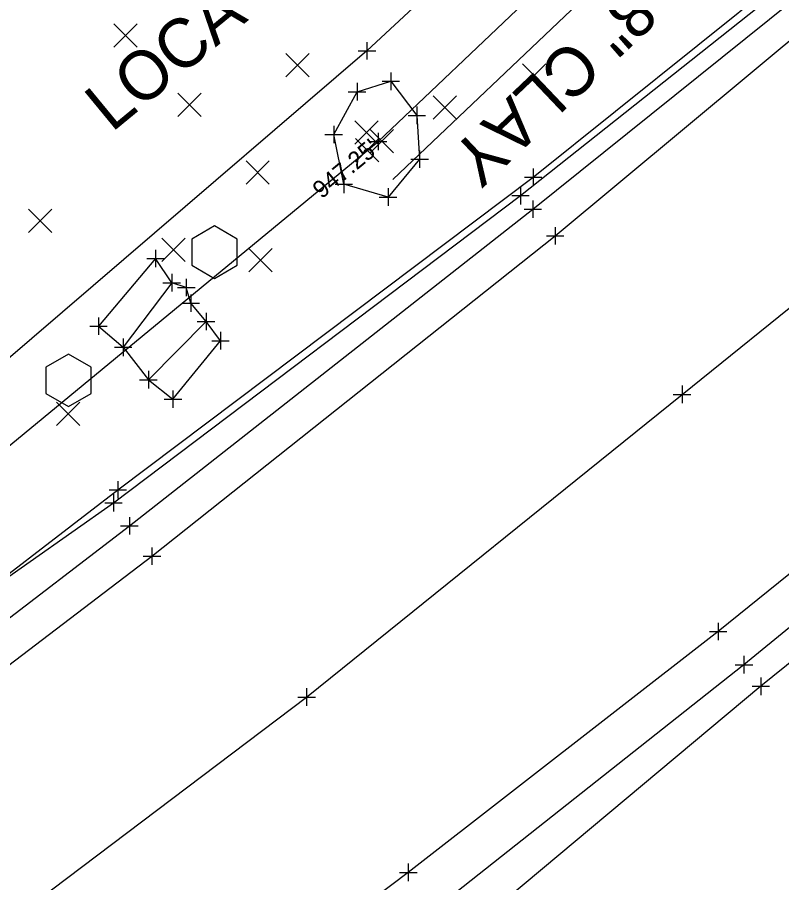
# Model space of a CAD drawing. Extents: x -4 to 139204, y -4 to 477121.
# Drawn here: x 139035.52 to 139079.26, y 476967.42 to 477016.92 of the extents above; entities that cross this region are included whole.
import ezdxf

# ---------------------------------------------------------------- set-up
doc = ezdxf.new("R2010")
doc.units = 0
for name, color, linetype in [('DR_X_Storm_Sewer', 7, 'Continuous'), ('DR_X_Text', 7, 'Continuous'), ('GE_X_Alignment', 7, 'Continuous'), ('GE_X_Alignment_100_Bearings', 7, 'Continuous'), ('GE_X_Alignment_100_Distances', 7, 'Continuous'), ('PM_X_Edge_Line', 7, 'Continuous'), ('PM_X_Surveyed_Line', 7, 'Continuous'), ('PV_X_COP', 7, 'Continuous'), ('PV_X_EOP', 7, 'Continuous'), ('PV_X_Shoulder', 7, 'Continuous'), ('PV_X_Shoulder_Aggregate', 7, 'Continuous'), ('RD_X_Concrete_Pad', 7, 'Continuous'), ('RD_X_Fence', 7, 'Continuous'), ('RD_X_GR_Lt', 7, 'Continuous'), ('RW_X_Esmt_SH', 7, 'Continuous'), ('SC_Scratch1', 7, 'Continuous'), ('SV_X_Text', 7, 'Continuous')]:
    doc.layers.add(name, color=color, linetype=linetype)

msp = doc.modelspace()

# ---------------------------------------------------------------- linework, layer by layer
at = {"layer": 'DR_X_Storm_Sewer'}
for p in [(139072.001, 477024.857), (138978.284, 476945.603)]:
    msp.add_line(p, (139056.168, 477009.808), dxfattribs=at)
at = {"layer": 'DR_X_Text'}
msp.add_line((139057.01, 477007.643), (139071.222, 477021.15), dxfattribs=at)
at = {"layer": 'GE_X_Alignment'}
for p, q in [((139041.05, 477015.206), (139042.384, 477016.541)), ((139041.05, 477016.541), (139042.384, 477015.206)), ((139050.88, 477013.504), (139052.214, 477014.84)), ((139050.88, 477014.84), (139052.214, 477013.504)), ((139064.431, 477012.923), (139065.765, 477014.258)), ((139064.431, 477014.258), (139065.765, 477012.923)), ((139044.7, 477011.238), (139046.034, 477012.573)), ((139044.7, 477012.573), (139046.034, 477011.238)), ((139059.326, 477011.084), (139060.66, 477012.418)), ((139059.326, 477012.418), (139060.66, 477011.084)), ((139054.839, 477009.653), (139056.173, 477010.988)), ((139054.839, 477010.988), (139056.173, 477009.653)), ((139055.708, 477009.166), (139057.042, 477010.502)), ((139055.708, 477010.502), (139057.042, 477009.166)), ((139054.876, 477008.658), (139056.21, 477009.993)), ((139054.876, 477009.993), (139056.21, 477008.658)), ((139048.608, 477007.38), (139049.942, 477008.715)), ((139048.608, 477008.715), (139049.942, 477007.38)), ((139036.17, 477004.601), (139037.504, 477005.935)), ((139036.17, 477005.935), (139037.504, 477004.601)), ((139043.783, 477002.952), (139045.117, 477004.287)), ((139043.783, 477004.287), (139045.117, 477002.952)), ((139048.767, 477002.362), (139050.101, 477003.698)), ((139048.767, 477003.698), (139050.101, 477002.362)), ((139037.762, 476993.565), (139039.096, 476994.9)), ((139037.762, 476994.9), (139039.096, 476993.565))]:
    msp.add_line(p, q, dxfattribs=at)
at = {"layer": 'GE_X_Alignment_100_Bearings'}
for p, q in [((139055.528, 477015.497), (139055.528, 477014.497)), ((139055.028, 477014.997), (139056.028, 477014.997)), ((139055.528, 477014.997), (139055.528, 477014.997)), ((139056.894, 477013.757), (139056.894, 477012.757)), ((139054.959, 477013.161), (139054.959, 477012.161)), ((139056.394, 477013.257), (139057.394, 477013.257)), ((139056.894, 477013.257), (139056.894, 477013.257)), ((139054.459, 477012.661), (139055.459, 477012.661)), ((139054.959, 477012.661), (139054.959, 477012.661)), ((139058.383, 477011.807), (139058.383, 477010.807)), ((139057.883, 477011.307), (139058.883, 477011.307)), ((139058.383, 477011.307), (139058.383, 477011.307)), ((139053.626, 477010.708), (139053.626, 477009.708)), ((139053.126, 477010.208), (139054.126, 477010.208)), ((139053.626, 477010.208), (139053.626, 477010.208)), ((139058.543, 477009.298), (139058.543, 477008.298)), ((139058.043, 477008.798), (139059.043, 477008.798)), ((139058.543, 477008.798), (139058.543, 477008.798)), ((139065.043, 477008.277), (139065.043, 477007.277)), ((139054.202, 477007.867), (139054.202, 477006.867)), ((139064.543, 477007.777), (139065.543, 477007.777)), ((139065.043, 477007.777), (139065.043, 477007.777)), ((139053.702, 477007.367), (139054.702, 477007.367)), ((139054.202, 477007.367), (139054.202, 477007.367)), ((139056.734, 477007.135), (139056.734, 477006.135)), ((139064.316, 477007.215), (139064.316, 477006.215)), ((139056.234, 477006.635), (139057.234, 477006.635)), ((139056.734, 477006.635), (139056.734, 477006.635)), ((139063.816, 477006.715), (139064.816, 477006.715)), ((139064.316, 477006.715), (139064.316, 477006.715)), ((139065.015, 477006.445), (139065.015, 477005.445)), ((139064.515, 477005.945), (139065.515, 477005.945)), ((139065.015, 477005.945), (139065.015, 477005.945)), ((139066.294, 477004.913), (139066.294, 477003.913)), ((139066.294, 477004.913), (139066.294, 477003.913)), ((139065.794, 477004.413), (139066.794, 477004.413)), ((139065.794, 477004.413), (139066.794, 477004.413)), ((139066.294, 477004.413), (139066.294, 477004.413)), ((139066.294, 477004.413), (139066.294, 477004.413)), ((139043.433, 477003.617), (139043.433, 477002.617)), ((139042.933, 477003.117), (139043.933, 477003.117)), ((139043.433, 477003.117), (139043.433, 477003.117)), ((139044.354, 477002.237), (139044.354, 477001.237)), ((139043.854, 477001.737), (139044.854, 477001.737)), ((139044.354, 477001.737), (139044.354, 477001.737)), ((139045.19, 477001.96), (139045.19, 477000.96)), ((139044.69, 477001.46), (139045.69, 477001.46)), ((139045.19, 477001.46), (139045.19, 477001.46)), ((139045.455, 477001.071), (139045.455, 477000.071)), ((139044.955, 477000.571), (139045.955, 477000.571)), ((139045.455, 477000.571), (139045.455, 477000.571)), ((139040.166, 476999.754), (139040.166, 476998.754)), ((139046.32, 477000.018), (139046.32, 476999.018)), ((139039.666, 476999.254), (139040.666, 476999.254)), ((139040.166, 476999.254), (139040.166, 476999.254)), ((139045.82, 476999.518), (139046.82, 476999.518)), ((139046.32, 476999.518), (139046.32, 476999.518)), ((139047.149, 476998.921), (139047.149, 476997.921)), ((139041.578, 476998.542), (139041.578, 476997.542)), ((139046.649, 476998.421), (139047.649, 476998.421)), ((139047.149, 476998.421), (139047.149, 476998.421)), ((139041.078, 476998.042), (139042.078, 476998.042)), ((139041.578, 476998.042), (139041.578, 476998.042)), ((139043.019, 476996.689), (139043.019, 476995.689)), ((139042.519, 476996.189), (139043.519, 476996.189)), ((139043.019, 476996.189), (139043.019, 476996.189)), ((139073.558, 476995.85), (139073.558, 476994.85)), ((139073.558, 476995.85), (139073.558, 476994.85)), ((139044.427, 476995.578), (139044.427, 476994.578)), ((139073.058, 476995.35), (139074.058, 476995.35)), ((139073.058, 476995.35), (139074.058, 476995.35)), ((139073.558, 476995.35), (139073.558, 476995.35)), ((139073.558, 476995.35), (139073.558, 476995.35)), ((139043.927, 476995.078), (139044.927, 476995.078)), ((139044.427, 476995.078), (139044.427, 476995.078)), ((139041.279, 476990.39), (139041.279, 476989.39)), ((139040.779, 476989.89), (139041.779, 476989.89)), ((139041.279, 476989.89), (139041.279, 476989.89)), ((139041.029, 476989.648), (139041.029, 476988.648)), ((139040.529, 476989.148), (139041.529, 476989.148)), ((139041.029, 476989.148), (139041.029, 476989.148)), ((139041.935, 476988.328), (139041.935, 476987.328)), ((139041.435, 476987.828), (139042.435, 476987.828)), ((139041.935, 476987.828), (139041.935, 476987.828)), ((139043.226, 476986.596), (139043.226, 476985.596)), ((139043.226, 476986.596), (139043.226, 476985.596)), ((139042.726, 476986.096), (139043.726, 476986.096)), ((139042.726, 476986.096), (139043.726, 476986.096)), ((139043.226, 476986.096), (139043.226, 476986.096)), ((139043.226, 476986.096), (139043.226, 476986.096)), ((139075.62, 476982.289), (139075.62, 476981.289)), ((139075.62, 476982.289), (139075.62, 476981.289)), ((139075.12, 476981.789), (139076.12, 476981.789)), ((139075.12, 476981.789), (139076.12, 476981.789)), ((139075.62, 476981.789), (139075.62, 476981.789)), ((139075.62, 476981.789), (139075.62, 476981.789)), ((139077.102, 476980.39), (139077.102, 476979.39)), ((139076.602, 476979.89), (139077.602, 476979.89)), ((139077.102, 476979.89), (139077.102, 476979.89)), ((139078.061, 476979.154), (139078.061, 476978.154)), ((139052.078, 476978.539), (139052.078, 476977.539)), ((139052.078, 476978.539), (139052.078, 476977.539)), ((139077.561, 476978.654), (139078.561, 476978.654)), ((139078.061, 476978.654), (139078.061, 476978.654)), ((139051.578, 476978.039), (139052.578, 476978.039)), ((139051.578, 476978.039), (139052.578, 476978.039)), ((139052.078, 476978.039), (139052.078, 476978.039)), ((139052.078, 476978.039), (139052.078, 476978.039)), ((139057.894, 476968.512), (139057.894, 476967.512)), ((139057.894, 476968.512), (139057.894, 476967.512)), ((139057.394, 476968.012), (139058.394, 476968.012)), ((139057.394, 476968.012), (139058.394, 476968.012)), ((139057.894, 476968.012), (139057.894, 476968.012)), ((139057.894, 476968.012), (139057.894, 476968.012))]:
    msp.add_line(p, q, dxfattribs=at)
at = {"layer": 'GE_X_Alignment_100_Distances'}
for p, q in [((139056.168, 477010.308), (139056.168, 477009.308)), ((139055.668, 477009.808), (139056.668, 477009.808)), ((139056.168, 477009.808), (139056.168, 477009.808))]:
    msp.add_line(p, q, dxfattribs=at)
at = {"layer": 'PM_X_Edge_Line'}
for points in [[(138923.242, 476898.186), (138964.692, 476927.855), (139004.314, 476956.805), (139026.754, 476973.572), (139043.226, 476986.096), (139066.294, 477004.413), (139084.97, 477019.976), (139103.96, 477036.155), (139120.378, 477050.406), (139142.062, 477069.904), (139165.575, 477091.057)], [(139119.978, 477018.535), (139108.07, 477008.289), (139096.43, 476998.562), (139075.62, 476981.789), (139057.894, 476968.012), (139018.116, 476938.023), (138977.717, 476908.355), (138952.937, 476890.592), (138936.689, 476878.892)]]:
    msp.add_lwpolyline(points, dxfattribs=at)
at = {"layer": 'PM_X_Surveyed_Line'}
msp.add_lwpolyline([(138930.184, 476888.564), (138972.007, 476918.562), (139012.493, 476948.198), (139029.811, 476961.233), (139052.078, 476978.039), (139073.558, 476995.35), (139089.175, 477007.916), (139110.846, 477026.03), (139111.346, 477026.745)], dxfattribs=at)
at = {"layer": 'PV_X_COP'}
msp.add_lwpolyline([(138930.195, 476888.554), (138972.007, 476918.562), (139012.493, 476948.198), (139029.811, 476961.233), (139052.078, 476978.039), (139073.558, 476995.35), (139089.175, 477007.916), (139110.846, 477026.03), (139129.377, 477042.526), (139155.719, 477066.268), (139171.584, 477080.905)], dxfattribs=at)
at = {"layer": 'PV_X_EOP'}
for points in [[(138923.266, 476898.028), (138964.692, 476927.855), (139004.314, 476956.805), (139026.754, 476973.572), (139043.226, 476986.096), (139066.294, 477004.413), (139084.97, 477019.976), (139103.96, 477036.155), (139120.378, 477050.406), (139142.062, 477069.904), (139165.559, 477091.096)], [(139119.987, 477018.511), (139108.07, 477008.289), (139096.43, 476998.562), (139075.62, 476981.789), (139057.894, 476968.012), (139018.116, 476938.023), (138977.717, 476908.355), (138952.937, 476890.592), (138936.542, 476879.008)]]:
    msp.add_lwpolyline(points, dxfattribs=at)
at = {"layer": 'PV_X_Shoulder'}
for points in [[(138921.874, 476900.032), (138963.408, 476929.378), (138972.798, 476935.952), (138978.522, 476940.169), (138981.386, 476942.476), (139003.06, 476958.542), (139025.401, 476975.169), (139041.935, 476987.828), (139065.015, 477005.945), (139083.976, 477021.177), (139103.138, 477037.313), (139119.211, 477051.78), (139140.599, 477071.456), (139163.948, 477092.808)], [(139183.638, 477072.424), (139153.919, 477045.299), (139136.787, 477030.023), (139126.343, 477020.832), (139109.649, 477006.831), (139097.905, 476996.885), (139077.102, 476979.89), (139059.387, 476965.891), (139020.106, 476935.561), (139003.351, 476922.965), (138997.924, 476918.666), (138993.965, 476914.098), (138990.512, 476910.309), (138981.306, 476903.856), (138956.564, 476885.614), (138940.343, 476873.773)]]:
    msp.add_lwpolyline(points, dxfattribs=at)
at = {"layer": 'PV_X_Shoulder_Aggregate'}
for points in [[(138921.157, 476900.979), (138962.753, 476930.499), (138971.584, 476937.069), (138977.481, 476941.526), (138980.594, 476943.61), (138988.422, 476949.897), (138998.433, 476958.567), (139001.441, 476961.07), (139021.93, 476975.729), (139041.029, 476989.148), (139064.316, 477006.715), (139083.388, 477021.859), (139091.2, 477028.559), (139091.618, 477030.237), (139093.456, 477032.075), (139094.302, 477031.202), (139095.586, 477032.478), (139102.652, 477038.046), (139118.491, 477052.663), (139139.94, 477072.231), (139163.129, 477093.583)], [(139124.206, 477016.86), (139110.781, 477005.495), (139098.924, 476995.454), (139078.061, 476978.654), (139060.667, 476964.123), (139021.044, 476934.127), (139004.817, 476921.429), (138999.267, 476916.949), (138995.343, 476912.815), (138991.494, 476909.144)]]:
    msp.add_lwpolyline(points, dxfattribs=at)
at = {"layer": 'RD_X_Concrete_Pad'}
for p, q in [((139044.354, 477001.737), (139041.578, 476998.042)), ((139043.019, 476996.189), (139046.32, 476999.518))]:
    msp.add_line(p, q, dxfattribs=at)
msp.add_lwpolyline([(139047.149, 476998.421), (139046.32, 476999.518), (139045.455, 477000.571), (139045.19, 477001.46), (139044.354, 477001.737), (139043.433, 477003.117), (139040.166, 476999.254), (139041.578, 476998.042), (139043.019, 476996.189), (139044.427, 476995.078)], close=True, dxfattribs=at)
at = {"layer": 'RD_X_Fence'}
msp.add_lwpolyline([(139114.124, 477069.425), (139097.626, 477050.067), (139068.264, 477026.835), (139055.528, 477014.997), (139027.688, 476991.135), (139019.001, 476984.321), (139015.388, 476979.86)], dxfattribs=at)
at = {"layer": 'RD_X_GR_Lt'}
msp.add_lwpolyline([(139020.21, 476982.913), (139024.42, 476980.958), (139030.898, 476981.914), (139041.279, 476989.89), (139065.043, 477007.777), (139083.881, 477022.893), (139095.593, 477032.486), (139103.613, 477039.235), (139110.37, 477044.947), (139114.423, 477051.669), (139114.509, 477056.44)], dxfattribs=at)
at = {"layer": 'RW_X_Esmt_SH'}
for points in [[(139045.51, 477002.735), (139046.808, 477001.985), (139048.106, 477002.735), (139048.106, 477004.235), (139046.808, 477004.985), (139045.51, 477004.235), (139045.51, 477002.735)], [(139037.147, 476995.397), (139038.445, 476994.647), (139039.743, 476995.397), (139039.743, 476996.897), (139038.445, 476997.647), (139037.147, 476996.897), (139037.147, 476995.397)]]:
    msp.add_lwpolyline(points, dxfattribs=at)
at = {"layer": 'SC_Scratch1'}
msp.add_lwpolyline([(139056.894, 477013.257), (139058.383, 477011.307), (139058.543, 477008.798), (139056.734, 477006.635), (139054.202, 477007.367), (139053.626, 477010.208), (139054.959, 477012.661)], close=True, dxfattribs=at)

# ---------------------------------------------------------------- texts
at = {"layer": 'DR_X_Text'}
msp.add_text('18" CLAY', height=2.8, rotation=223.5457, dxfattribs=at).set_placement((139071.951, 477020.323))
at = {"layer": 'SC_Scratch1'}
msp.add_text("947.25'", height=1, rotation=39.501, dxfattribs=at).set_placement((139052.938, 477006.497))
at = {"layer": 'SV_X_Text'}
msp.add_text('LOCATION APPROX.', height=2.8, rotation=39.4837, dxfattribs=at).set_placement((139040.919, 477010.293))

doc.saveas('drawing.dxf')
